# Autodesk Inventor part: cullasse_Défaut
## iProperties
Shininess: 64.0
Length Units: 11269
Angle Units: 11279
Time Units: 11290
Mass Units: 11283
Length Display Precision: 3
Angle Display Precision: 2
Compacted: True
Part Number: cullasse_Défaut
Document SubType Name: Modeling
Created: 2006-01
Material: Par défaut
Designer: riri
Density: 0.0
Volumn: 0.0
Area: 0.0
PropertySet Name: Model Information
Control State: 0
Master: False
Checked Out: False
Author: riri
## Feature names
1. Base1
